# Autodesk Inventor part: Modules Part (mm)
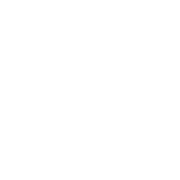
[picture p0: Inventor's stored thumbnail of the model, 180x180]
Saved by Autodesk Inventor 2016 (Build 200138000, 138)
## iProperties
Created: 2014-08
Part Number: Modules Part (mm)
Material: Generic
Document SubType Name: Modeling
Designer: Wally
Density: 1 g/cm^3
Appearance: Default
Author: Wally
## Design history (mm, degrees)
node "Sketch1"
